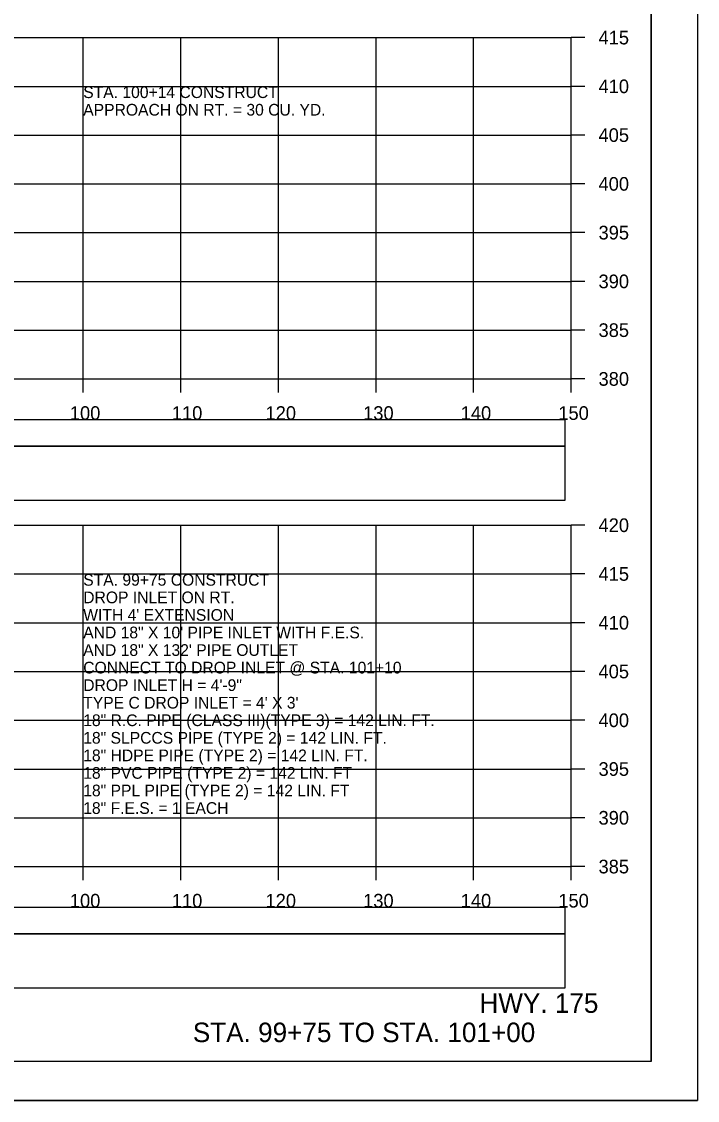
# Model space of a CAD drawing. Extents: x -37291014 to -37290680, y -936053 to -933067.
# Drawn here: x -37290749.4 to -37290680.2, y -935840 to -935729.3 of the extents above; entities that cross this region are included whole.
import ezdxf

# ---------------------------------------------------------------- set-up
doc = ezdxf.new("R2010")
doc.units = 0
for name, color, linetype in [('Default', 7, 'Continuous'), ('R_Axis', 7, 'Continuous'), ('R_Axis Annot', 7, 'Continuous'), ('R_Border', 7, 'Continuous'), ('R_Draft', 7, 'Continuous'), ('R_Grid', 7, 'Continuous'), ('R_No Plot', 7, 'Continuous'), ('R_Water Annot', 7, 'Continuous')]:
    doc.layers.add(name, color=color, linetype=linetype)

msp = doc.modelspace()

# ---------------------------------------------------------------- linework, layer by layer
at = {"layer": 'Default'}
for points in [[(-37290992.48, -935772.89), (-37290693.72, -935772.89), (-37290693.72, -935770.19), (-37290992.48, -935770.19)], [(-37290992.48, -935778.41), (-37290693.72, -935778.41), (-37290693.72, -935772.89), (-37290992.48, -935772.89)], [(-37290992.48, -935822.89), (-37290693.72, -935822.89), (-37290693.72, -935820.19), (-37290992.48, -935820.19)], [(-37290992.48, -935828.41), (-37290693.72, -935828.41), (-37290693.72, -935822.89), (-37290992.48, -935822.89)]]:
    msp.add_lwpolyline(points, close=True, dxfattribs=at)
at = {"layer": 'R_Axis'}
for p, q in [((-37290693.1, -935765.99), (-37290693.1, -935730.99)), ((-37290691.7, -935730.99), (-37290693.1, -935730.99)), ((-37290691.7, -935735.99), (-37290693.1, -935735.99)), ((-37290691.7, -935740.99), (-37290693.1, -935740.99)), ((-37290691.7, -935745.99), (-37290693.1, -935745.99)), ((-37290691.7, -935750.99), (-37290693.1, -935750.99)), ((-37290691.7, -935755.99), (-37290693.1, -935755.99)), ((-37290691.7, -935760.99), (-37290693.1, -935760.99)), ((-37290993.1, -935765.99), (-37290693.1, -935765.99)), ((-37290743.1, -935767.39), (-37290743.1, -935765.99)), ((-37290733.1, -935767.39), (-37290733.1, -935765.99)), ((-37290723.1, -935767.39), (-37290723.1, -935765.99)), ((-37290713.1, -935767.39), (-37290713.1, -935765.99)), ((-37290703.1, -935767.39), (-37290703.1, -935765.99)), ((-37290693.1, -935767.39), (-37290693.1, -935765.99)), ((-37290691.7, -935765.99), (-37290693.1, -935765.99)), ((-37290693.1, -935815.99), (-37290693.1, -935780.99)), ((-37290691.7, -935780.99), (-37290693.1, -935780.99)), ((-37290691.7, -935785.99), (-37290693.1, -935785.99)), ((-37290691.7, -935790.99), (-37290693.1, -935790.99)), ((-37290691.7, -935795.99), (-37290693.1, -935795.99)), ((-37290691.7, -935800.99), (-37290693.1, -935800.99)), ((-37290691.7, -935805.99), (-37290693.1, -935805.99)), ((-37290691.7, -935810.99), (-37290693.1, -935810.99)), ((-37290993.1, -935815.99), (-37290693.1, -935815.99)), ((-37290743.1, -935817.39), (-37290743.1, -935815.99)), ((-37290733.1, -935817.39), (-37290733.1, -935815.99)), ((-37290723.1, -935817.39), (-37290723.1, -935815.99)), ((-37290713.1, -935817.39), (-37290713.1, -935815.99)), ((-37290703.1, -935817.39), (-37290703.1, -935815.99)), ((-37290693.1, -935817.39), (-37290693.1, -935815.99)), ((-37290691.7, -935815.99), (-37290693.1, -935815.99))]:
    msp.add_line(p, q, dxfattribs=at)
at = {"layer": 'R_Border'}
for q in [(-37290684.92, -935630.53), (-37291001.1, -935835.99)]:
    msp.add_line((-37290684.92, -935835.99), q, dxfattribs=at)
at = {"layer": 'R_Grid'}
for p, q in [((-37290993.1, -935730.99), (-37290693.1, -935730.99)), ((-37290743.1, -935765.99), (-37290743.1, -935730.99)), ((-37290733.1, -935765.99), (-37290733.1, -935730.99)), ((-37290723.1, -935765.99), (-37290723.1, -935730.99)), ((-37290713.1, -935765.99), (-37290713.1, -935730.99)), ((-37290703.1, -935765.99), (-37290703.1, -935730.99)), ((-37290693.1, -935765.99), (-37290693.1, -935730.99)), ((-37290993.1, -935735.99), (-37290693.1, -935735.99)), ((-37290993.1, -935740.99), (-37290693.1, -935740.99)), ((-37290993.1, -935745.99), (-37290693.1, -935745.99)), ((-37290993.1, -935750.99), (-37290693.1, -935750.99)), ((-37290993.1, -935755.99), (-37290693.1, -935755.99)), ((-37290993.1, -935760.99), (-37290693.1, -935760.99)), ((-37290993.1, -935765.99), (-37290693.1, -935765.99)), ((-37290993.1, -935780.99), (-37290693.1, -935780.99)), ((-37290743.1, -935815.99), (-37290743.1, -935780.99)), ((-37290733.1, -935815.99), (-37290733.1, -935780.99)), ((-37290723.1, -935815.99), (-37290723.1, -935780.99)), ((-37290713.1, -935815.99), (-37290713.1, -935780.99)), ((-37290703.1, -935815.99), (-37290703.1, -935780.99)), ((-37290693.1, -935815.99), (-37290693.1, -935780.99)), ((-37290993.1, -935785.99), (-37290693.1, -935785.99)), ((-37290993.1, -935790.99), (-37290693.1, -935790.99)), ((-37290993.1, -935795.99), (-37290693.1, -935795.99)), ((-37290993.1, -935800.99), (-37290693.1, -935800.99)), ((-37290993.1, -935805.99), (-37290693.1, -935805.99)), ((-37290993.1, -935810.99), (-37290693.1, -935810.99)), ((-37290993.1, -935815.99), (-37290693.1, -935815.99))]:
    msp.add_line(p, q, dxfattribs=at)
at = {"layer": 'R_No Plot'}
msp.add_line((-37291013.5, -935839.96), (-37290680.17, -935839.96), dxfattribs=at)
for points in [[(-37291013.51, -935626.63), (-37290680.17, -935626.63), (-37290680.17, -935839.97), (-37291013.51, -935839.97)], [(-37290767.18, -935630.53), (-37290747.56, -935630.53), (-37290747.56, -935640.41), (-37290731.45, -935640.41), (-37290708.25, -935640.41), (-37290708.25, -935664.74), (-37290684.92, -935664.74), (-37290684.92, -935835.99), (-37291001.1, -935835.99), (-37291001.1, -935630.53)]]:
    msp.add_lwpolyline(points, close=True, dxfattribs=at)

# ---------------------------------------------------------------- texts
at = {"layer": 'R_Axis Annot'}
for s, p in [('415', (-37290690.3, -935731.69)), ('410', (-37290690.3, -935736.69)), ('405', (-37290690.3, -935741.69)), ('400', (-37290690.3, -935746.69)), ('395', (-37290690.3, -935751.69)), ('390', (-37290690.3, -935756.69)), ('385', (-37290690.3, -935761.69)), ('380', (-37290690.3, -935766.69)), ('100', (-37290744.47, -935770.19)), ('110', (-37290734.02, -935770.19)), ('120', (-37290724.42, -935770.19)), ('130', (-37290714.42, -935770.19)), ('140', (-37290704.42, -935770.19)), ('150', (-37290694.42, -935770.19)), ('420', (-37290690.3, -935781.69)), ('415', (-37290690.3, -935786.69)), ('410', (-37290690.3, -935791.69)), ('405', (-37290690.3, -935796.69)), ('400', (-37290690.3, -935801.69)), ('395', (-37290690.3, -935806.69)), ('390', (-37290690.3, -935811.69)), ('385', (-37290690.3, -935816.69)), ('100', (-37290744.47, -935820.19)), ('110', (-37290734.02, -935820.19)), ('120', (-37290724.42, -935820.19)), ('130', (-37290714.42, -935820.19)), ('140', (-37290704.42, -935820.19)), ('150', (-37290694.42, -935820.19))]:
    msp.add_text(s, height=1.4, dxfattribs=at).set_placement(p)
at = {"layer": 'R_Draft'}
for s, p in [('HWY. 175', (-37290702.5, -935830.99)), ('STA. 99+75 TO STA. 101+00', (-37290731.87, -935833.99))]:
    msp.add_text(s, height=2, dxfattribs=at).set_placement(p)
at = {"layer": 'R_Water Annot'}
for s, p in [('STA. 100+14 CONSTRUCT', (-37290743.1, -935737.19)), ('APPROACH ON RT. = 30 CU. YD.', (-37290743.1, -935738.99)), ('STA. 99+75 CONSTRUCT', (-37290743.1, -935787.19)), ('DROP INLET ON RT.', (-37290743.1, -935788.99)), ("WITH 4' EXTENSION", (-37290743.1, -935790.79)), ('AND 18" X 10\' PIPE INLET WITH F.E.S.', (-37290743.1, -935792.59)), ('AND 18" X 132\' PIPE OUTLET', (-37290743.1, -935794.39)), ('CONNECT TO DROP INLET @ STA. 101+10', (-37290743.1, -935796.19)), ('DROP INLET H = 4\'-9"', (-37290743.1, -935797.99)), ("TYPE C DROP INLET = 4' X 3'", (-37290743.1, -935799.79)), ('18" R.C. PIPE (CLASS III)(TYPE 3) = 142 LIN. FT.', (-37290743.1, -935801.59)), ('18" SLPCCS PIPE (TYPE 2) = 142 LIN. FT.', (-37290743.1, -935803.39)), ('18" HDPE PIPE (TYPE 2) = 142 LIN. FT.', (-37290743.1, -935805.19)), ('18" PVC PIPE (TYPE 2) = 142 LIN. FT', (-37290743.1, -935806.99)), ('18" PPL PIPE (TYPE 2) = 142 LIN. FT', (-37290743.1, -935808.79)), ('18" F.E.S. = 1 EACH', (-37290743.1, -935810.59))]:
    msp.add_text(s, height=1.2, dxfattribs=at).set_placement(p)

doc.saveas('drawing.dxf')
